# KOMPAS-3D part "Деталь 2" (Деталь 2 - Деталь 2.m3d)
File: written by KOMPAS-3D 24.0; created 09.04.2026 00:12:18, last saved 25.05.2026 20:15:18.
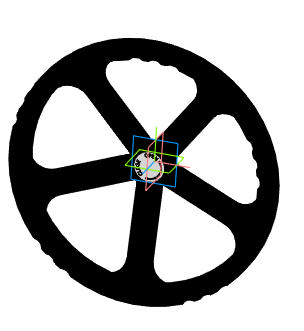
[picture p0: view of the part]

Document properties: Автор: mrdid; Полное имя файла: E:\Работа\Зайцев\АУТСОРС\Даня\GVKN1331N-2W-Fb-R Задвижка шиберная DN.ru Ду400-600 Ру4-6\исходные материалы\DN400\Деталь 2 - Деталь 2.m3d

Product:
- Body: Твердое тело1  | qty 1
    Масса: 6.481519
- Part/product: Деталь 2
    Масса: 6.481519
    additional columns: Типовые

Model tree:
1. Твердое тело1  (labels: Твердое тело1)
2. Масштабирование:1
3. Масштабирование : Твердое тело1
     Масштаб по оси Х = 1; Масштаб по оси Y = 1; Масштаб по оси Z = 1; Коэффициент = 1.16667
